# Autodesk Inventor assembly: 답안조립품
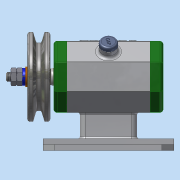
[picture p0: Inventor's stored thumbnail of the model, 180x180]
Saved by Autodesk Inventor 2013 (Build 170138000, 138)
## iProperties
Created: 2018-06
Part Number: 답안조립품
Document SubType Name: Assembly
Designer: Administrator
Author: Administrator
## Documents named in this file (16)
- C:\Users\Administrator\Desktop\480608V1008\답안조립품.iam
- C:\Users\Administrator\Desktop\480608V1008\본체.ipt
- C:\Users\Administrator\Desktop\480608V1008\뒤커버.ipt
- C:\Users\Administrator\Desktop\480608V1008\앞커버.ipt
- C:\Users\Administrator\Desktop\480608V1008\베어링 15x32x9.ipt
- C:\Users\Administrator\Desktop\480608V1008\오일 실 15 25 7.ipt
- C:\Users\Administrator\Desktop\480608V1008\볼트 M4x12.ipt
- C:\Users\Administrator\Desktop\480608V1008\축.ipt
- C:\Users\Administrator\Desktop\480608V1008\키 3x3x12.ipt
- 키 3x3x12.ipt
- C:\Users\Administrator\Desktop\480608V1008\V벨트풀리.ipt
- C:\Users\Administrator\Desktop\480608V1008\와셔 8x17.ipt
- C:\Users\Administrator\Desktop\480608V1008\스프링와셔 8.ipt
- C:\Users\Administrator\Desktop\480608V1008\너트 M8.ipt
- 너트 M8.ipt
- C:\Users\Administrator\Desktop\480608V1008\고무캡.ipt
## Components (2 placed, 2 different names)
1. V벨트풀리:1 — 각도:2
2. 고무캡:1
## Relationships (1: Angle 1)
- 각도:2 [Angle]: V벨트풀리:1
